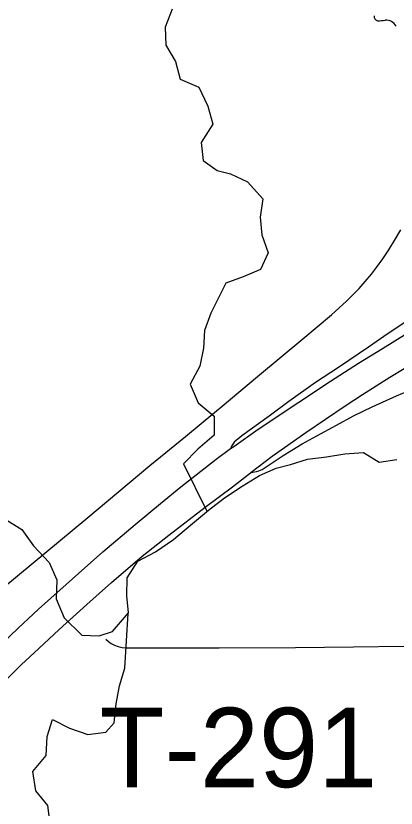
# Model space of a CAD drawing. Extents: x 0 to 34, y 0 to 22.
# Drawn here: x 4.589 to 4.861, y 18.033 to 18.6 of the extents above; entities that cross this region are included whole.
import ezdxf

# ---------------------------------------------------------------- set-up
doc = ezdxf.new("R2010")
doc.units = 0
for name, color, linetype in [('GM_X_County_Road', 7, 'Continuous'), ('GM_X_Interchange_Ramps', 7, 'Continuous'), ('GM_X_Interstate_Route', 7, 'Continuous'), ('GM_X_Minor_River', 7, 'Continuous'), ('GM_X_State_Shield', 7, 'Continuous'), ('GM_X_Township_Road', 7, 'Continuous'), ('GM_X_Township_Road_Text', 7, 'Continuous')]:
    doc.layers.add(name, color=color, linetype=linetype)

msp = doc.modelspace()

# ---------------------------------------------------------------- linework, layer by layer
at = {"layer": 'GM_X_County_Road'}
msp.add_lwpolyline([(4.582256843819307, 18.192011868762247), (4.639528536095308, 18.239490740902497), (4.6853483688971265, 18.277897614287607), (4.710818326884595, 18.298670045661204), (4.723345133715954, 18.309214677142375), (4.73694071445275, 18.320343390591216), (4.762242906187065, 18.34160667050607), (4.794634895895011, 18.36855552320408), (4.81515252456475, 18.385618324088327), (4.820707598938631, 18.39070110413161), (4.825827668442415, 18.395380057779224), (4.8306122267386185, 18.40008379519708), (4.834787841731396, 18.40455148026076), (4.8392865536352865, 18.409553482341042), (4.843673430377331, 18.414785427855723), (4.8474078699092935, 18.419576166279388), (4.851782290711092, 18.42564699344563), (4.856032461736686, 18.432177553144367), (4.86019565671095, 18.438782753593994), (4.864768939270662, 18.446437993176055)], dxfattribs=at)
at = {"layer": 'GM_X_Interchange_Ramps'}
for points in [[(4.870504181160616, 18.38203303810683), (4.855547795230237, 18.372190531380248), (4.841473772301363, 18.362546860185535), (4.820024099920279, 18.348081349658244), (4.803787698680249, 18.337157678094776), (4.784699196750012, 18.32368018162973), (4.770525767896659, 18.313247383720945), (4.756849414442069, 18.30350430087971), (4.750946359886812, 18.299073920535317), (4.745627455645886, 18.294649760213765), (4.74355829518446, 18.29167338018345), (4.743272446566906, 18.291101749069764), (4.742918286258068, 18.28993976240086)], [(4.757184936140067, 18.272734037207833), (4.758931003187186, 18.27311929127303), (4.761422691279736, 18.27367228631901), (4.763249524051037, 18.274119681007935), (4.7656293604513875, 18.27511386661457), (4.780455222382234, 18.28504960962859), (4.79410051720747, 18.293444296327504), (4.804725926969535, 18.29921684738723), (4.818632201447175, 18.306828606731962), (4.830835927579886, 18.313390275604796), (4.844220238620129, 18.319815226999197), (4.861537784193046, 18.32768797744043), (4.879774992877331, 18.33529977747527), (4.905754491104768, 18.34579471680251), (4.924122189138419, 18.352878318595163), (4.9510212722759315, 18.362590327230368), (4.967816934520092, 18.367971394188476), (4.978833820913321, 18.370985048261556), (4.991826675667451, 18.374004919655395), (5.002539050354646, 18.376142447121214), (5.0107162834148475, 18.377677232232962), (5.023839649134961, 18.379777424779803), (5.029842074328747, 18.380740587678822)]]:
    msp.add_lwpolyline(points, dxfattribs=at)
at = {"layer": 'GM_X_Interstate_Route'}
for points in [[(4.573663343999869, 18.144955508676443), (4.591148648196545, 18.161446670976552), (4.605663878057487, 18.17514169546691), (4.634197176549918, 18.200704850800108), (4.651514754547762, 18.216040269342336), (4.674772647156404, 18.235669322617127), (4.692748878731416, 18.250681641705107), (4.707425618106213, 18.262717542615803), (4.732665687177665, 18.2825143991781), (4.742918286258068, 18.28993976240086), (4.745198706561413, 18.291586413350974), (4.762684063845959, 18.303951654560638), (4.791708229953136, 18.323251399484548), (4.814469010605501, 18.33809592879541), (4.834427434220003, 18.35112605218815), (4.851583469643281, 18.361683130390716), (4.878134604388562, 18.37801277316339)], [(4.5767391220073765, 18.11905683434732), (4.593180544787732, 18.13521865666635), (4.605862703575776, 18.147068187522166), (4.6204959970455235, 18.160583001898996), (4.640137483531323, 18.178416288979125), (4.657834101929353, 18.194298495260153), (4.679712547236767, 18.21310737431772), (4.698800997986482, 18.228156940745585), (4.724718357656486, 18.2480842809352), (4.744297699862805, 18.262593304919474), (4.757184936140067, 18.272734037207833), (4.757644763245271, 18.273094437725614), (4.772744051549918, 18.28458356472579), (4.796809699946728, 18.30154074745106), (4.824926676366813, 18.320573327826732), (4.837397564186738, 18.328557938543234), (4.856871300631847, 18.341140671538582), (4.887616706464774, 18.35973828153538)]]:
    msp.add_lwpolyline(points, dxfattribs=at)
at = {"layer": 'GM_X_Minor_River'}
for points in [[(4.701182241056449, 18.60440179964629), (4.696256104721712, 18.591469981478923), (4.696657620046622, 18.578541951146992), (4.703525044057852, 18.566763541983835), (4.70696822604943, 18.554221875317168), (4.720292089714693, 18.54853626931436), (4.726782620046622, 18.53485445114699), (4.730225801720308, 18.521932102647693), (4.721875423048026, 18.508996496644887), (4.723417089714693, 18.496068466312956), (4.733320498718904, 18.488860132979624), (4.742835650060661, 18.48658929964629), (4.755019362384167, 18.48090179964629), (4.766074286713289, 18.46874839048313), (4.764189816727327, 18.455437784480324), (4.7653526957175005, 18.442894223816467), (4.769936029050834, 18.429971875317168), (4.764246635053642, 18.4181802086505), (4.752079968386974, 18.41284119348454), (4.73953072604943, 18.408263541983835), (4.728909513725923, 18.386956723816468), (4.724362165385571, 18.37440558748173), (4.723619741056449, 18.361860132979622), (4.7209776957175, 18.348928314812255), (4.714146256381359, 18.3359927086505), (4.719875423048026, 18.322693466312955), (4.731305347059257, 18.313202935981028), (4.73132618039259, 18.29951543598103), (4.7195458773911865, 18.289617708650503), (4.709288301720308, 18.278958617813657), (4.725663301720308, 18.24571808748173)], [(4.649051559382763, 18.156072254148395), (4.658485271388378, 18.159134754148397), (4.6698811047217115, 18.172456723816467), (4.668720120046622, 18.184619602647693), (4.669081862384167, 18.197547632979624), (4.676672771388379, 18.20934308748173), (4.68921822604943, 18.216201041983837), (4.702142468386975, 18.224962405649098), (4.714301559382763, 18.235242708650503), (4.727222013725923, 18.245903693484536), (4.738623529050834, 18.25466316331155), (4.751167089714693, 18.26304195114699), (4.763712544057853, 18.270663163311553), (4.775498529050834, 18.276000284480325), (4.785769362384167, 18.27867452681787), (4.797937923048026, 18.282490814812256), (4.811632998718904, 18.284028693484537), (4.824566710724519, 18.286327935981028), (4.8378829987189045, 18.28710445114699), (4.849309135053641, 18.280274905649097), (4.8618621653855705, 18.282191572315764)], [(4.581000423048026, 18.239858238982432), (4.5936197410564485, 18.23211202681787), (4.602144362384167, 18.220502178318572), (4.61332618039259, 18.208558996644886), (4.618841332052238, 18.196134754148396), (4.618324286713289, 18.18246808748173), (4.623860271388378, 18.16890748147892), (4.636559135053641, 18.15661202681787), (4.649051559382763, 18.156072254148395)], [(4.653672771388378, 18.087110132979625), (4.659727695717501, 18.093744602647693), (4.661227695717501, 18.107432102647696), (4.663490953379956, 18.12036202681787), (4.667276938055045, 18.132913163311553), (4.669837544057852, 18.172115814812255)], [(4.6587239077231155, 18.015119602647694), (4.6466026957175, 18.01604384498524), (4.637735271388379, 18.004129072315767), (4.625324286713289, 18.000119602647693), (4.614216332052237, 18.00789232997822), (4.613975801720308, 18.02154384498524), (4.6122276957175, 18.0347900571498), (4.603722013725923, 18.045263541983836), (4.601591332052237, 18.058882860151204), (4.611222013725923, 18.070432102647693), (4.611739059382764, 18.084098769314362), (4.615682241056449, 18.096307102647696), (4.62789815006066, 18.090072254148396), (4.640841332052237, 18.0853677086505), (4.653672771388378, 18.087110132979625)]]:
    msp.add_lwpolyline(points, dxfattribs=at)
at = {"layer": 'GM_X_State_Shield'}
for centre, radius, start, end in [((4.848702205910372, 18.59909453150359), 0.0030816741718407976, 171.9583861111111, 258.30661388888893), ((4.84916944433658, 18.619568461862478), 0.023517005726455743, 267.33899444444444, 280.6038555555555), ((4.85398093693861, 18.587987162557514), 0.00847971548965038, 29.748380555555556, 93.27174722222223)]:
    msp.add_arc(centre, radius, start, end, dxfattribs=at)
at = {"layer": 'GM_X_Township_Road'}
msp.add_lwpolyline([(4.653857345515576, 18.1536111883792), (4.655708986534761, 18.152082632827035), (4.657672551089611, 18.15056028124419), (4.659959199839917, 18.149466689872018), (4.662575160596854, 18.14837928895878), (4.665408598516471, 18.147726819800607), (4.668024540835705, 18.147397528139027), (4.734703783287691, 18.14750937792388), (4.789291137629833, 18.147726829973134), (4.810212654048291, 18.14804994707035), (4.8309104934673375, 18.148267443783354), (4.866869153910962, 18.148596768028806), (4.910992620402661, 18.14870860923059), (4.940961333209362, 18.14881424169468), (4.986066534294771, 18.14936103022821), (5.032371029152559, 18.14990164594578), (5.071921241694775, 18.150448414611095)], dxfattribs=at)

# ---------------------------------------------------------------- texts
at = {"layer": 'GM_X_Township_Road_Text'}
msp.add_text('T-291', height=0.05681818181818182, rotation=1e-05, dxfattribs=at).set_placement((4.649324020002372, 18.047774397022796))

doc.saveas('drawing.dxf')
